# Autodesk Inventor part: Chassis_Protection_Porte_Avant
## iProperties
Created: 2009-01
Part Number: Chassis_Protection_Porte_Avant
Document SubType Name: Sheet Metal
Designer: claivier
Author: claivier
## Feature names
1. Extrusion3
2. Extrusion4
3. Chanfrein de coin1
4. Perçage1 [Hole]
5. Perçage2 [Hole]
6. Perçage3 [Hole]
7. Plaque1
8. Pli1
9. Plaque2
10. Pli2
11. Plaque3
12. Pli3
13. Couper1
14. Couper2
15. Couper3
16. Couper4
17. Couper6
18. Couper7
19. Couper8
